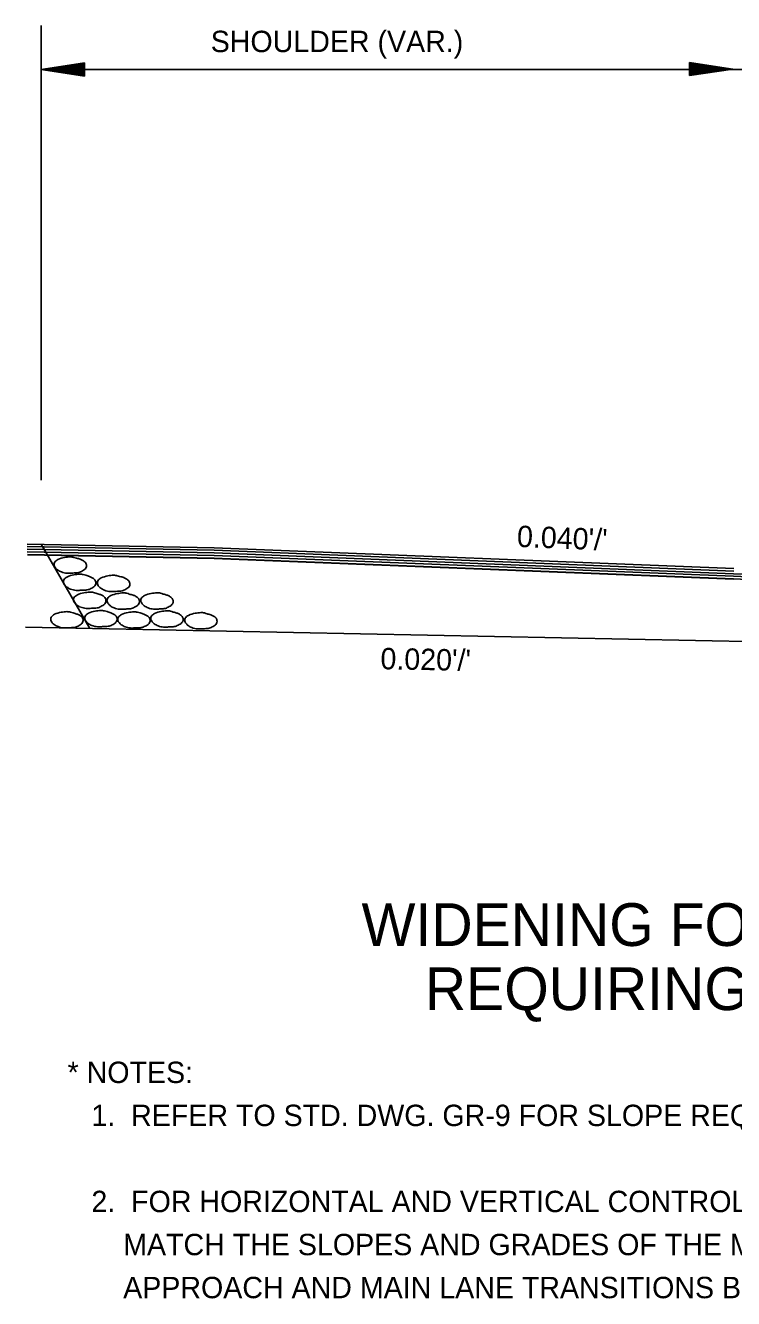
# Model space of a CAD drawing. Extents: x 1929624 to 1936506, y 596315 to 605721.
# Drawn here: x 1933803.6 to 1934004.9, y 603935.3 to 604297 of the extents above; entities that cross this region are included whole.
import ezdxf

# ---------------------------------------------------------------- set-up
doc = ezdxf.new("R2010")
doc.units = 0
doc.layers.add('Default', color=7, linetype='Continuous')

msp = doc.modelspace()

# ---------------------------------------------------------------- linework, layer by layer
at = {"layer": 'Default'}
for p, q in [((1933808.09, 604167.83), (1933808.09, 604296.97)), ((1933820.42, 604286.31), (1933808.09, 604284.47)), ((1933820.42, 604285.99), (1933810.16, 604284.47)), ((1933820.42, 604285.67), (1933812.27, 604284.47)), ((1933820.42, 604282.6), (1933820.42, 604286.31)), ((1933992.35, 604286.44), (1934004.68, 604284.57)), ((1933992.35, 604286.44), (1933992.35, 604282.72)), ((1933992.35, 604286.12), (1934002.61, 604284.57)), ((1933992.35, 604285.8), (1934000.49, 604284.57)), ((1933992.35, 604285.5), (1933998.43, 604284.57)), ((1933808.09, 604284.47), (1934138.62, 604284.47)), ((1933820.42, 604282.6), (1933808.09, 604284.47)), ((1933820.42, 604282.92), (1933810.16, 604284.47)), ((1933820.42, 604283.24), (1933812.27, 604284.47)), ((1933820.42, 604285.38), (1933814.34, 604284.47)), ((1933820.42, 604283.53), (1933814.34, 604284.47)), ((1933820.42, 604285.06), (1933816.41, 604284.47)), ((1933820.42, 604283.85), (1933816.41, 604284.47)), ((1933820.42, 604284.74), (1933818.48, 604284.47)), ((1933820.42, 604284.17), (1933818.48, 604284.47)), ((1933992.35, 604285.18), (1933996.36, 604284.57)), ((1933992.35, 604284.86), (1933994.29, 604284.57)), ((1933992.35, 604282.72), (1934004.68, 604284.57)), ((1933992.35, 604283.98), (1933996.36, 604284.57)), ((1933992.35, 604283.36), (1934000.49, 604284.57)), ((1933992.35, 604283.04), (1934002.61, 604284.57)), ((1933992.35, 604283.66), (1933998.43, 604284.57)), ((1933992.35, 604284.3), (1933994.29, 604284.57)), ((1933804.13, 604149.66), (1933857.3, 604148.61)), ((1933804.13, 604148.93), (1933857.3, 604147.87)), ((1933804.16, 604148.19), (1933857.3, 604147.13)), ((1933821.92, 604125.68), (1933808.09, 604149.58)), ((1934004.92, 604142.7), (1933857.3, 604148.61)), ((1933804.18, 604147.45), (1933857.3, 604146.39)), ((1933804.2, 604146.71), (1933857.25, 604145.65)), ((1933804.2, 604146.61), (1933857.3, 604145.56)), ((1934004.82, 604139.75), (1933857.2, 604145.65)), ((1934004.87, 604141.23), (1933857.25, 604147.13)), ((1934004.87, 604140.49), (1933857.25, 604146.39)), ((1934004.92, 604141.96), (1933857.3, 604147.87)), ((1934004.82, 604139.65), (1933857.3, 604145.56)), ((1934004.86, 604141.23), (1934139.51, 604135.84)), ((1934004.8, 604139.75), (1934139.46, 604134.36)), ((1934004.82, 604140.49), (1934139.48, 604135.1)), ((1933803.65, 604126.05), (1934197.03, 604118.22))]:
    msp.add_line(p, q, dxfattribs=at)
for points in [[(1933816.37, 604146.02), (1933814.74, 604145.82), (1933812.87, 604145.23), (1933811.94, 604144.39), (1933811.79, 604143.8), (1933812.23, 604142.82), (1933812.78, 604142.32), (1933813.86, 604141.73), (1933815.43, 604141.39), (1933816.22, 604141.39), (1933817.45, 604141.44), (1933818.78, 604141.59), (1933819.86, 604142.03), (1933820.85, 604142.91), (1933820.99, 604143.51), (1933820.7, 604144.39), (1933819.96, 604144.98), (1933819.22, 604145.33), (1933818.14, 604145.67), (1933817.4, 604145.87), (1933816.37, 604146.02)], [(1933819.04, 604141.13), (1933817.42, 604140.93), (1933815.55, 604140.34), (1933814.56, 604139.5), (1933814.42, 604138.91), (1933814.86, 604137.93), (1933815.4, 604137.44), (1933816.48, 604136.85), (1933818.06, 604136.5), (1933818.89, 604136.5), (1933820.12, 604136.55), (1933821.45, 604136.7), (1933822.49, 604137.14), (1933823.52, 604138.03), (1933823.67, 604138.62), (1933823.37, 604139.5), (1933822.63, 604140.09), (1933821.89, 604140.44), (1933820.76, 604140.78), (1933820.07, 604140.98), (1933819.04, 604141.13)], [(1933828.7, 604140.81), (1933827.08, 604140.61), (1933825.21, 604140.02), (1933824.22, 604139.18), (1933824.08, 604138.59), (1933824.52, 604137.61), (1933825.06, 604137.12), (1933826.14, 604136.53), (1933827.72, 604136.18), (1933828.55, 604136.18), (1933829.78, 604136.23), (1933831.11, 604136.38), (1933832.15, 604136.82), (1933833.18, 604137.71), (1933833.33, 604138.3), (1933833.03, 604139.18), (1933832.29, 604139.77), (1933831.56, 604140.12), (1933830.42, 604140.46), (1933829.74, 604140.66), (1933828.7, 604140.81)], [(1933821.9, 604136.01), (1933820.28, 604135.81), (1933818.41, 604135.22), (1933817.43, 604134.39), (1933817.28, 604133.84), (1933817.72, 604132.86), (1933818.26, 604132.32), (1933819.34, 604131.73), (1933820.92, 604131.38), (1933821.76, 604131.38), (1933822.99, 604131.43), (1933824.31, 604131.58), (1933825.35, 604132.07), (1933826.38, 604132.91), (1933826.53, 604133.55), (1933826.23, 604134.43), (1933825.5, 604135.03), (1933824.76, 604135.37), (1933823.63, 604135.67), (1933822.94, 604135.91), (1933821.9, 604136.01)], [(1933831.42, 604135.79), (1933829.79, 604135.59), (1933827.92, 604135), (1933826.94, 604134.16), (1933826.79, 604133.62), (1933827.23, 604132.64), (1933827.78, 604132.1), (1933828.86, 604131.51), (1933830.43, 604131.16), (1933831.27, 604131.16), (1933832.5, 604131.21), (1933833.83, 604131.36), (1933834.86, 604131.85), (1933835.89, 604132.69), (1933836.04, 604133.33), (1933835.75, 604134.21), (1933835.01, 604134.8), (1933834.27, 604135.15), (1933833.14, 604135.44), (1933832.45, 604135.69), (1933831.42, 604135.79)], [(1933841, 604135.8), (1933839.37, 604135.61), (1933837.5, 604135.02), (1933836.57, 604134.18), (1933836.42, 604133.64), (1933836.86, 604132.66), (1933837.4, 604132.11), (1933838.49, 604131.52), (1933840.06, 604131.18), (1933840.85, 604131.18), (1933842.08, 604131.23), (1933843.41, 604131.38), (1933844.49, 604131.87), (1933845.47, 604132.7), (1933845.62, 604133.34), (1933845.33, 604134.23), (1933844.59, 604134.82), (1933843.85, 604135.16), (1933842.77, 604135.46), (1933842.03, 604135.71), (1933841, 604135.8)], [(1933815.42, 604130.47), (1933813.79, 604130.28), (1933811.92, 604129.69), (1933810.99, 604128.85), (1933810.84, 604128.26), (1933811.28, 604127.28), (1933811.82, 604126.78), (1933812.91, 604126.19), (1933814.48, 604125.85), (1933815.27, 604125.85), (1933816.5, 604125.9), (1933817.83, 604126.05), (1933818.91, 604126.49), (1933819.89, 604127.37), (1933820.04, 604127.96), (1933819.75, 604128.85), (1933819.01, 604129.44), (1933818.27, 604129.78), (1933817.19, 604130.13), (1933816.45, 604130.33), (1933815.42, 604130.47)], [(1933825.06, 604130.79), (1933823.44, 604130.6), (1933821.57, 604130.01), (1933820.63, 604129.17), (1933820.48, 604128.58), (1933820.93, 604127.6), (1933821.47, 604127.1), (1933822.55, 604126.51), (1933824.13, 604126.17), (1933824.91, 604126.17), (1933826.14, 604126.22), (1933827.47, 604126.36), (1933828.55, 604126.81), (1933829.54, 604127.69), (1933829.69, 604128.28), (1933829.39, 604129.17), (1933828.65, 604129.76), (1933827.91, 604130.1), (1933826.83, 604130.45), (1933826.09, 604130.65), (1933825.06, 604130.79)], [(1933834.46, 604130.43), (1933832.84, 604130.24), (1933830.97, 604129.65), (1933830.03, 604128.81), (1933829.88, 604128.22), (1933830.33, 604127.23), (1933830.87, 604126.74), (1933831.95, 604126.15), (1933833.52, 604125.81), (1933834.31, 604125.81), (1933835.54, 604125.86), (1933836.87, 604126), (1933837.95, 604126.45), (1933838.94, 604127.33), (1933839.08, 604127.92), (1933838.79, 604128.81), (1933838.05, 604129.4), (1933837.31, 604129.74), (1933836.23, 604130.09), (1933835.49, 604130.29), (1933834.46, 604130.43)], [(1933843.83, 604130.7), (1933842.21, 604130.5), (1933840.34, 604129.91), (1933839.4, 604129.07), (1933839.26, 604128.53), (1933839.7, 604127.55), (1933840.24, 604127), (1933841.32, 604126.41), (1933842.9, 604126.07), (1933843.69, 604126.07), (1933844.92, 604126.12), (1933846.24, 604126.27), (1933847.33, 604126.76), (1933848.31, 604127.6), (1933848.46, 604128.23), (1933848.16, 604129.12), (1933847.43, 604129.71), (1933846.69, 604130.06), (1933845.6, 604130.35), (1933844.87, 604130.6), (1933843.83, 604130.7)], [(1933853.48, 604130.19), (1933851.85, 604129.99), (1933849.98, 604129.4), (1933849.05, 604128.56), (1933848.9, 604128.02), (1933849.34, 604127.04), (1933849.89, 604126.5), (1933850.97, 604125.91), (1933852.54, 604125.56), (1933853.33, 604125.56), (1933854.56, 604125.61), (1933855.89, 604125.76), (1933856.97, 604126.25), (1933857.96, 604127.09), (1933858.1, 604127.73), (1933857.81, 604128.61), (1933857.07, 604129.2), (1933856.33, 604129.55), (1933855.25, 604129.84), (1933854.51, 604130.09), (1933853.48, 604130.19)]]:
    msp.add_spline(points, degree=3, dxfattribs=at)

# ---------------------------------------------------------------- texts
for s, height, rotation, p in [('SHOULDER (VAR.)', 6.075, 360, (1933856.3, 604289.39)), ("0.040'/'", 6.075, 357.7094, (1933943.24, 604148.86)), ("0.020'/'", 6.075, 358.8537, (1933904.49, 604114.11)), ('WIDENING FOR GUARDRAIL', 12.15, 360, (1933899.15, 604035.48)), ('REQUIRING EARTHWORK', 12.15, 360, (1933917.15, 604017.26)), ('* NOTES:  ', 6.075, 360, (1933815.62, 603996.55)), ('   1.  REFER TO STD. DWG. GR-9 FOR SLOPE REQUIREMENTS BEHIND GUARDRAIL.', 6.075, 360, (1933815.62, 603984.32)), ('   2.  FOR HORIZONTAL AND VERTICAL CONTROL, THE GUARDRAIL WIDENING SHALL', 6.075, 360, (1933815.62, 603959.87)), ('       MATCH THE SLOPES AND GRADES OF THE MAIN LANES.  CONSTRUCT BRIDGE ', 6.075, 360, (1933815.62, 603947.64)), ('       APPROACH AND MAIN LANE TRANSITIONS BEFORE PAVING GUARDRAIL WIDENING.', 6.075, 360, (1933815.62, 603935.42))]:
    msp.add_text(s, height=height, rotation=rotation, dxfattribs=at).set_placement(p)

doc.saveas('drawing.dxf')
